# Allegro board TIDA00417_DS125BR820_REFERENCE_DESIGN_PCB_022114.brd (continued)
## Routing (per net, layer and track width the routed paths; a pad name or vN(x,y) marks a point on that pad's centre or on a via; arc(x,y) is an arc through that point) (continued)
N167546690: length 2.9
  BOTTOM w0.203: R50.2 SW11.1
N167546691: length 2.9
  BOTTOM w0.203: R51.2 SW11.2
N167546692: length 2.9
  BOTTOM w0.203: R54.2 SW11.3
N167546693: length 2.9
  BOTTOM w0.203: R56.2 SW11.4
N167546694: length 2.9
  BOTTOM w0.203: R58.2 SW11.5
N167547371: length 3
  TOP w0.203: R57.2 SW12.4
N167547671: length 3
  TOP w0.203: R61.2 SW12.6
N167547831: length 3
  TOP w0.203: R59.2 SW12.5
N167548151: length 3
  TOP w0.203: R55.2 SW12.3
N167549111: length 2.9
  TOP w0.203: R52.2 SW12.1
N167549751: length 3
  TOP w0.203: R53.2 SW12.2
N167550950: length 2.9
  BOTTOM w0.203: R72.2 SW18.1
N167550951: length 2.9
  BOTTOM w0.203: R73.2 SW18.2
N167550952: length 2.9
  BOTTOM w0.203: R75.2 SW18.3
N167550953: length 2.9
  BOTTOM w0.203: R76.2 SW18.4
N167550954: length 2.9
  BOTTOM w0.203: R77.2 SW18.5
N167550955: length 2.9
  BOTTOM w0.203: R78.2 SW18.6
N167551251: length 2.9
  BOTTOM w0.203: R62.2 SW14.1
N167552231: length 2.9
  BOTTOM w0.203: R66.2 SW14.2
N167554851: length 2.8
  BOTTOM w0.203: R70.2 SW14.6
N167555071: length 2.9
  BOTTOM w0.203: R67.2 SW14.3
N167555691: length 2.9
  BOTTOM w0.203: R68.2 SW14.4
N167556734: length 2.9
  BOTTOM w0.203: R69.2 SW14.5
N167558911: length 2.9
  TOP w0.203: R47.2 SW10.4
N167559111: length 2.9
  TOP w0.203: R48.2 SW10.5
N167559271: length 2.9
  TOP w0.203: R45.2 SW10.3
N167559851: length 2.9
  TOP w0.203: R46.2 SW10.2
N167560011: length 2.9
  TOP w0.203: R49.2 SW10.6
N167560171: length 2.9
  TOP w0.203: R44.2 SW10.1
N167582101: length 3.6
  TOP w0.203: SW6.3 190.8,16.32 R30.2
N167582261: length 3.6
  TOP w0.203: SW6.1 190.8,11.24 R26.2
N167582481: length 3.6
  TOP w0.203: R28.2 190.8,13.78 SW6.2
N167598171: length 3.2
  TOP w0.203: R65.2 SW15.3
N167598391: length 3.2
  TOP w0.203: R63.2 SW15.1
N167598551: length 3.2
  TOP w0.203: R64.2 SW15.2
N167665790: length 1.9
  TOP w0.508: D2.2 R71.1
N167695010: length 1.9
  TOP w0.508: D1.2 R34.1

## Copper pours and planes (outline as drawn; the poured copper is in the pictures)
GND on TOP (solid shape): outline of 376 points within 121.82,73.18 156.08,82.85
GND on BOTTOM (solid shape): outline of 377 points within 97.66,35.22 107.33,69.48
GND on TOP: 180.97,95.15 173.48,95.15 173.1,94.77 173.1,92.35 173.35,92.1 180.97,92.1 181.23,92.35 181.23,94.89
GND on TOP: 75.84,49.43 76.26,49 80.03,49 80.48,49.45 80.48,57.44 80.31,57.61 76.23,57.61 75.84,57.22
GND on TOP: 20.35,77.57 20.35,69.77 23.77,69.77 23.77,77.57
GND on BOTTOM: 134.19,50.34 134.19,46.44 134.38,46.26 142.29,46.26 142.83,46.8 142.83,50.6 142.57,50.86 134.71,50.86
GND on GND-1, GND-2, GND-3, GND-4: 0.76,0.76 0.76,100.84 221.49,100.84 221.49,0.76
VDD on TOP: 78.35,57.84 80.35,57.84 80.82,58.32 80.82,59.08 80.19,59.72 76.43,59.72 76.15,59.44 76.15,58.62 76.81,57.96 78.23,57.96
VDD on BOTTOM: 133.95,47.76 133.95,49.56 133.77,49.75 132.6,49.75 131.99,49.14 131.99,46.6 132.4,46.19 133.61,46.19 133.82,46.39 133.82,47.62
VDD on PWR-1: 92.25,34.93 92.25,50.22 72.65,50.22 72.65,77.25 30.45,77.25 30.45,82.39 0.76,82.39 0.76,100.84 172.69,100.84 172.69,92.88 168.8,92.88 168.8,83.86 205.23,83.86 205.23,52.37 142.68,52.37 142.68,34.93
VIN on TOP: 177.42,91.59 170.05,91.59 169.42,90.96 169.42,85.62 170.18,84.86 180.97,84.86 181.99,85.88 181.99,89.31 181.1,90.2 178.44,90.2 177.8,90.83 177.8,91.21
VIN on SIG-1: 167.05,89 167.05,99.54 168.35,100.84 214.56,100.84 216.45,98.95 216.45,95.84 217.19,95.1 220.55,95.1 221.22,94.42 221.22,84.26 219.62,82.66 203.5,82.66 201.6,84.56 201.6,93.57 200.89,94.29 198.7,94.29 191.5,87.1 186.63,87.1 186.59,87.06 168.99,87.06
VIN on PWR-1: 72.65,0.76 72.65,49.46 91.49,49.46 91.49,34.16 143.44,34.16 143.44,51.61 205.99,51.61 205.99,84.62 169.56,84.62 169.56,92.12 173.45,92.12 173.45,100.84 221.49,100.84 221.49,0.76
QSFP_VCC_3P3V on TOP: 24.38,77.53 24.38,77.52 24.19,77.52 24.19,75.43 24.38,75.24 24.38,69.75 28.58,69.75 28.58,77.53
QSFP_VCC_3P3V on PWR-1: 0.76,0.76 0.76,81.63 29.69,81.63 29.69,76.49 71.88,76.49 71.88,0.76
VIH on SIG-2: 170.32,0.76 170.32,0.77 161,0.77 161,100.84 221.49,100.84 221.49,0.76

Small or netless copper shapes (teardrops, artwork), in the pictures only: 27 on TOP, 20 on BOTTOM

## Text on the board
BOTTOM: UL94V-0 | MADE IN U.S. | 10-BOTTOM
Ref Des/Assembly Bottom: BOTTOM-ASSY
Board Geometry/Soldermask Bottom: UL94V-0 | MADE IN U.S. | BOTTOM-MASK
Package Geometry/Pastemask Bottom: BOTTOM-PASTE
Ref Des/Silkscreen Bottom: EGR_LN2_P | EGR_LN2_N | EGR_LN4_P | EGR_LN1_P | EGR_LN1_N | EGR_LN4_N | EGR_LN3_N | EGR_LN3_P | 16 | 15 | 14 | 13 | 12 | 11 | 10 | 9 | 1 | 2 | 3 | 4 | 5 | 6 | 7 | 8 | ING_LN4_P | ING_LN2_P | ING_LN1_N | ING_LN1_P | ING_LN3_P | ING_LN4_N | ING_LN2_N | ING_LN3_N | VDD, 2.5V MODE | 3.3V MODE | VIH | 2.5V MODE | VIN, 3.3V MODE | GND | QSFP_VCC_3P3V | NC | SCL | SDA | U4 | FEB-2014 | 305-PD-13-1124 | BOTTOM-SILK
TOP: 01-TOP
Ref Des/Assembly Top: TOP-ASSY
Board Geometry/Soldermask Top: TOP-MASK
Package Geometry/Pastemask Top: TOP-PASTE
Ref Des/Silkscreen Top: QSFP RESETL | QSFP OBSERVATION AND CONTROL HEADER | L1 | L19 | U20 | U39 | VDD, 2.5V MODE | 3.3V MODE | VIH | 2.5V MODE | RT2_SD_TH | GND | VIN, 3.3V MODE | ING ALL DONE | EGR ALL DONE | QSFP_VCC_3P3V | 9 | EGR_LN3_P | ING_LN4_P | 8 | 10 | 7 | EGR_LN3_N | ING_LN4_N | EGR_LN1_N | 11 | 6 | ING_LN3_P | 12 | EGR_LN1_P | ING_LN3_N | 5 | 13 | ING_LN2_P | 4 | EGR_LN2_N | 14 | ING_LN2_N | EGR_LN2_P | 3 | 15 | EGR_LN4_N | 2 | ING_LN1_P | 16 | EGR_LN4_P | 1 | ING_LN1_N | NC | SCL | SDA | RT1_SD_TH_READ_EN | U5 | U3 | REV E1 | SV601084 | TIDA00417 | TOP-SILK
GND-1: 02-GND-1
SIG-1: can lead to unwanted pair-to-pair | NOTE: The high-speed routing in this | (~7mil width, ~15mil spacing) which | crosstalk. It is recommended to use | PCB design uses loosely coupled traces | example 5mil trace, 6mil space) | tightly-coupled routing (for | and better crosstalk performance. | for better inter-pair isolation | 03-SIG-1
PWR-1: 04-PWR-1
GND-2: 05-GND-2
SIG-2: 06-SIG-2
GND-3: 07-GND-3
SIG-3: 08-SIG-3
GND-4: 09-GND-4
User.8: 3000 Patrick Henry Drive | COMPANY: | Santa Clara CA 95054 | Direct-408-329-5500 | Fax-408-747-1239 | 305-PD-13-1124 | DETAIL A. | DETAIL B. | DETAIL C. | DETAIL D. | 13.IMPEDANCE | 10.MINIMUM PLATING ON ALL THROUGH HOLES SHOULD BE 0.001 Cu. | 14.THIS BOARD IS ROHS COMPLAINT . | 15.ANY CHANGES MADE BY THE PCB FABRICATOR TO THE FILM OR | 12.BOARD DIMENSIONS ARE IN INCHES[MM]. | 11.DEBURR ALL SHARP EDGES. | 16.BACK DRILL -SEE DETAIL A,B,C AND D. | NOTES (UNLESS OTHERWISE SPECIFIED): | 9.MAXIMUM WARP AND TWIST SHALL NOT EXCEED .004 PER LINEAR INCH. | 5.SILKSCREEN : WHITE EPOXY INK. | 7.REMOVE THE NON-FUNCTIONAL PADS ON ALL INNER LAYERS. | 6.NO VENDOR LOGO OR NAME ON THE BOARD. | 1.BOARD THICKNESS : 90 +/- 9 MILS. | 8.PLATING : IMMERSION GOLD. | 2.DIELECTRIC : REFER STACK UP. | 4.SOLDERMASK : LPI GREEN | 3.NUMBER OF LAYERS: 10. | 8/20/8 REQUIRES 100 OHM +/-5% DIFFERENTIAL IMPEDANCE ON SIGNAL LAYERS. | 7.9 MIL REQUIRES 50 OHM +/-5% SINGLE-ENDED IMPEDANCE ON SIG-1 AND SIG-3 LAYERS. | 8 MIL REQUIRES 50 OHM +/-5% SINGLE-ENDED  IMPEDANCE ON TOP AND BOTTOM LAYERS. | 7/15/7 REQUIRES 100 OHM +/-5% DIFFERENTIAL IMPEDANCE ON TOP AND BOTTOM LAYERS. | THE GERBER FILES MUST BE APPROVED BY PACTRON. | TIDA00417_DS125BR810_REFERENCE_DESIGN | TITLE: | (SHOULD NOT BREAK THE SIGNAL PAD IN LAYER-6) | (SHOULD NOT BREAK THE SIGNAL PAD IN LAYER-8)
User.19: 6 | DS90LV048A 16P TSSOP
User.26: FAB
User.30: REV B STANDARD FOR CLASS 2 ASSEMBLIES. | 1.  THIS DRAWING IS VALID FOR PC P/N 138-016760-01(BOTTOM ASSEMBLY). | 2.  WORKMANSHIP IS TO MEET OR EXCEED THE IPC-A-610 | 3.  INSTALL RECEPTACLE PINS FOR RELAYS. | NOTES (UNLESS OTHERWISE SPECIFIED): | FARSIDE (POGOSDIDE)
User.34: FIGURE | SIZE | 8.0 | 10.0 | 10.01 | 10.02 | 10.03 | 10.04 | 14.567 | 22.047 | 39.37 | 40.0 | 41.339 | 98.425 | 125.0 | DRILL CHART: TOP to BOTTOM | ALL UNITS ARE IN MILS | TOLERANCE | +3.0/-8.0 | +3.0/-10.0 | +2.0/-2.0 | +3.0/-3.0 | PLATED | NON-PLATED | QTY | 74 | 646 | 6 | 4 | 76 | 3 | 40 | 10 | 2
User.35: TEXAS AND INSTRUMENTS | DATE:FEB 2014 | LAYER: | TIDA00417_DS125BR820_REFERENCE_DESIGN | 305-PD-13-1124 | Rev.1
User.38: 2.26 MIL | 0.7 MIL | 1.3 MIL | 12.00 MIL | 5.00 MIL | 12.0 MIL | 7.50 MIL | 5.0 MIL | THIS IS A 10 LAYER BOARD | BOTTOM SIDE SOLDER MASK | TOP SIDE SOLDER MASK | LAYER STACK-UP | FR408 | LAYER 1 | LAYER 2 | LAYER 3 | LAYER 4 | LAYER 6 | LAYER 7 | LAYER 8 | LAYER 9 | LAYER 10 | LAYER 5 | SIG-1 | TOP | GND-1 | PWR-1 | GND-4 | BOTTOM | SIG-3 | GND-3 | SIG-2 | GND-2
User.40: NOTES: | - DRILL SIZES LISTED IN LEGEND | ARE CONSIDERED FINISHED. | - VENDOR IS REQUIRED TO SELECT | TOOLING FOR OVERDRILLING. | - LEGEND DOES NOT SPECIFY DEPTH | INTO ADJACENT DIELECTRIC LAYER. | FIGURE | SIZE | 10.03 | BACKDRILL: TOP to GND-3 | ALL UNITS ARE IN MILS | TOLERANCE | +3.0/-10.0 | PLATED | QTY | 4
User.41: NOTES: | - DRILL SIZES LISTED IN LEGEND | ARE CONSIDERED FINISHED. | - VENDOR IS REQUIRED TO SELECT | TOOLING FOR OVERDRILLING. | - LEGEND DOES NOT SPECIFY DEPTH | INTO ADJACENT DIELECTRIC LAYER. | FIGURE | SIZE | 10.02 | BACKDRILL: BOTTOM to GND-4 | ALL UNITS ARE IN MILS | TOLERANCE | +3.0/-10.0 | PLATED | QTY | 6
User.42: NOTES: | - DRILL SIZES LISTED IN LEGEND | ARE CONSIDERED FINISHED. | - VENDOR IS REQUIRED TO SELECT | TOOLING FOR OVERDRILLING. | - LEGEND DOES NOT SPECIFY DEPTH | INTO ADJACENT DIELECTRIC LAYER. | FIGURE | SIZE | 10.01 | BACKDRILL: BOTTOM to GND-3 | ALL UNITS ARE IN MILS | TOLERANCE | +3.0/-10.0 | PLATED | QTY | 6
User.43: NOTES: | - DRILL SIZES LISTED IN LEGEND | ARE CONSIDERED FINISHED. | - VENDOR IS REQUIRED TO SELECT | TOOLING FOR OVERDRILLING. | - LEGEND DOES NOT SPECIFY DEPTH | INTO ADJACENT DIELECTRIC LAYER. | FIGURE | SIZE | 10.04 | BACKDRILL: TOP to GND-2 | ALL UNITS ARE IN MILS | TOLERANCE | +3.0/-10.0 | PLATED | QTY | 4
